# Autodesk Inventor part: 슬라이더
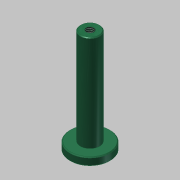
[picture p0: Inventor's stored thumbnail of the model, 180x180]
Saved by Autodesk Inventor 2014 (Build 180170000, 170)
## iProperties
Created: 2016-02
Part Number: 슬라이더
Material: 스테인리스강
Document SubType Name: Modeling
Designer: mduedu
Density: 8.08 g/cm^3
Appearance: 매끄러움 - 짙은 바다 녹색
Mass: 72.5507 g
Surface Area: 37.669 cm^2
Volume: 8.97904 cm^3
Author: mduedu
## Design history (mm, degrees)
sketch "스케치1"
  geometry: C1 r 12.5 at (0, 0); 1 further point
  constraints: 1 centre point, 1 coincident
  dimensions: "d0" = 25 diameter of C1
extrude "돌출1" new body sketch "스케치1" distance "d1" = 5; taper "d2" = 0 deg
sketch "스케치2"
  geometry: C1 r 6 at (0, 0); 1 further point
  constraints: 1 centre point, 1 coincident
  dimensions: "d3" = 12 diameter of C1
extrude "돌출2" join sketch "스케치2" distance "d4" = 60; taper "d5" = 0 deg
chamfer "모따기1" distance "d6" = 0.5; stored, may be unused: second distance "d7" = 2, angle "d8" = 45 deg
hole "구멍1" diameter "d11" = 4.917; stored, may be unused: countersink angle "d15" = 90 deg, drill point angle "d17" = 118 deg; dims "d9" = 10, "d10" = 10, "d12" = 10, "d13" = 4, "d14" = 2, "d16" = 12
chamfer "모따기2" distance "d18" = 0.5; stored, may be unused: second distance "d19" = 2, angle "d20" = 45 deg
sketch "스케치3"
  geometry: L1 (-12.5, 4.5)-(-12, 5) reference; L2 (-12, 5)-(-6, 5) reference; L3 (-6, 5)-(-6, 64.5) reference; L4 (-6, 64.5)-(-5.5, 65) reference; L5 (-5.5, 65)-(-2.458, 65) reference; L6 (-2.458, 65)-(-2.458, 53) reference; L7 (-2.458, 53)-(0, 51.523) reference; L8 (0, 51.523)-(2.458, 53) reference; L9 (2.458, 53)-(2.458, 65) reference; L10 (2.458, 65)-(5.5, 65) reference; L11 (5.5, 65)-(6, 64.5) reference; L12 (6, 64.5)-(6, 5) reference; L13 (6, 5)-(12, 5) reference; L14 (12, 5)-(12.5, 4.5) reference; L15 (12.5, 4.5)-(12.5, 0.5) reference; L16 (12.5, 0.5)-(12, 0) reference; L17 (12, 0)-(-12, 0) reference; L18 (-12, 0)-(-12.5, 0.5) reference; L19 (-12.5, 0.5)-(-12.5, 4.5) reference; 1 further point
  node "절단 모서리 투영1"
node "솔리드1"
